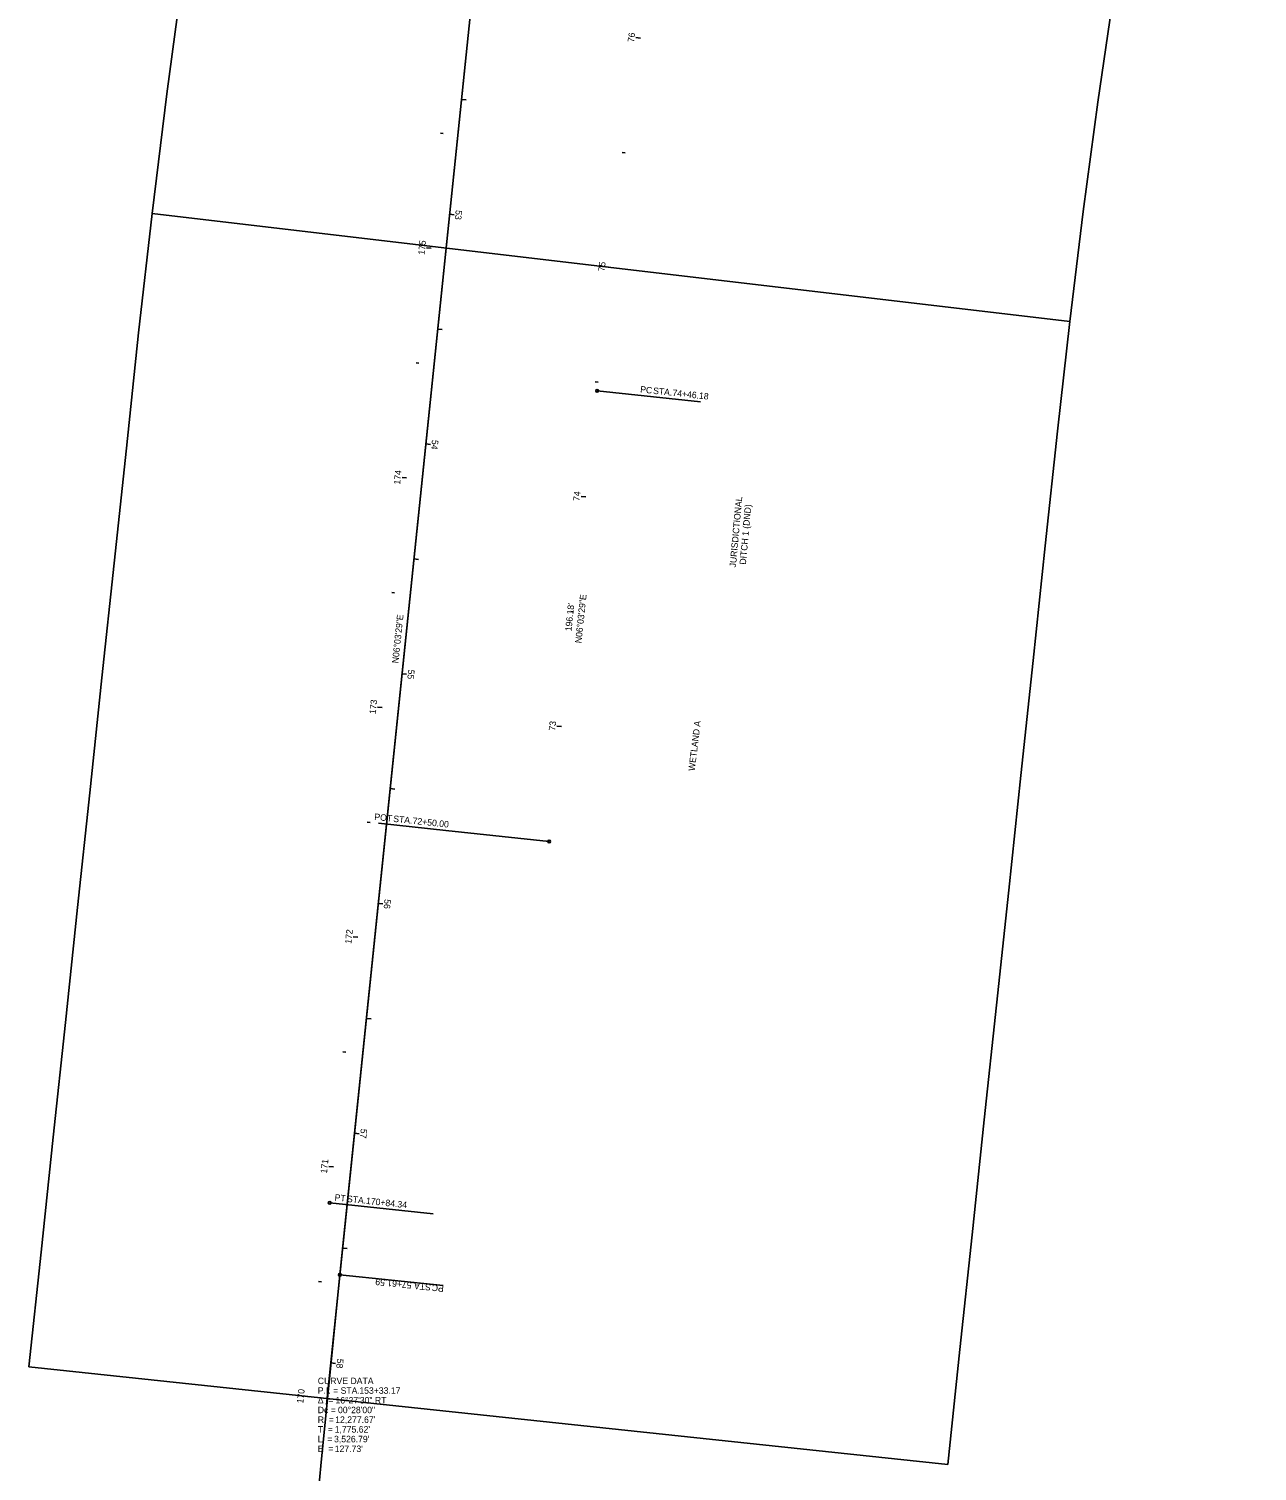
# Model space of a CAD drawing. Extents: x 172043 to 172958, y 249504 to 260295.
# Drawn here: x 172043 to 172574, y 253906 to 254530 of the extents above; entities that cross this region are included whole.
import ezdxf

# ---------------------------------------------------------------- set-up
doc = ezdxf.new("R2010")
doc.units = 0
for name, color, linetype in [('DR_X_Storm_Sewer', 7, 'Continuous'), ('LT_X_Poles', 7, 'Continuous'), ('PV_X_EOP', 7, 'Continuous'), ('RD_X_Fence', 7, 'Continuous'), ('RS_Raster1', 7, 'Continuous'), ('RW_X_CL_100_Bearings', 7, 'Continuous'), ('RW_X_CL_100_Curve_Data', 7, 'Continuous'), ('RW_X_CL_100_Distances', 7, 'Continuous'), ('RW_X_CL_100_Stations', 7, 'Continuous'), ('SC_Scratch1', 7, 'Continuous'), ('SV_X_Shot_Marker', 7, 'Continuous')]:
    doc.layers.add(name, color=color, linetype=linetype)

msp = doc.modelspace()

# ---------------------------------------------------------------- linework, layer by layer
at = {"layer": 'DR_X_Storm_Sewer'}
for points in [[(172095.96, 254450.44), (172493.22, 254403.68), (172499.07, 254451.2), (172505.42, 254498.65), (172512.28, 254546.03), (172519.63, 254593.34), (172527.5, 254640.57), (172535.86, 254687.71), (172544.72, 254734.76), (172554.08, 254781.71), (172563.94, 254828.56), (172574.32, 254875.56), (172184.15, 254963.66), (172172.96, 254913.01), (172162.22, 254862), (172152.03, 254810.88), (172142.38, 254759.66), (172133.28, 254708.34), (172124.72, 254656.92), (172116.71, 254605.42), (172109.24, 254553.83), (172102.33, 254502.17)], [(172042.63, 253950.99), (172440.4, 253908.78), (172445.67, 253958.5), (172450.95, 254008.22), (172456.23, 254057.94), (172461.5, 254107.66), (172466.78, 254157.38), (172472.06, 254207.1), (172477.34, 254256.82), (172482.61, 254306.54), (172487.87, 254356.1), (172493.22, 254403.68), (172095.96, 254450.44), (172090.14, 254398.64), (172084.85, 254348.76), (172079.57, 254299.04), (172074.29, 254249.32), (172069.02, 254199.6), (172063.74, 254149.88), (172058.46, 254100.16), (172053.18, 254050.44), (172047.91, 254000.71)]]:
    msp.add_lwpolyline(points, close=True, dxfattribs=at)
at = {"layer": 'PV_X_EOP'}
for p, q in [((172222, 254485.05), (172220.8, 254485.17)), ((172216.72, 254435.33), (172214.73, 254435.54)), ((172211.44, 254385.6), (172210.25, 254385.73)), ((172206.16, 254335.88), (172204.18, 254336.1)), ((172200.89, 254286.16), (172199.69, 254286.29)), ((172195.61, 254236.44), (172193.62, 254236.65)), ((172190.33, 254186.72), (172189.14, 254186.85)), ((172185.06, 254137), (172183.07, 254137.21)), ((172179.78, 254087.28), (172178.59, 254087.41)), ((172174.5, 254037.56), (172172.51, 254037.77)), ((172169.27, 253987.83), (172168.08, 253987.96)), ((172164.24, 253938.09), (172162.25, 253938.29))]:
    msp.add_line(p, q, dxfattribs=at)
at = {"layer": 'RW_X_CL_100_Bearings'}
for p, q in [((172288.6, 254373.57), (172333.35, 254368.82)), ((172193.92, 254186.34), (172223.15, 254183.24)), ((172267.9, 254178.49), (172223.15, 254183.24))]:
    msp.add_line(p, q, dxfattribs=at)
for centre in [(172288.6, 254373.57), (172267.9, 254178.49)]:
    msp.add_circle(centre, 0.6, dxfattribs=at)
at = {"layer": 'RW_X_CL_100_Stations'}
for p, q in [((172307.33, 254526.24), (172305.35, 254526.52)), ((172300.7, 254476.69), (172299.51, 254476.84)), ((172294.59, 254427.06), (172292.6, 254427.29)), ((172289.01, 254377.37), (172287.81, 254377.5)), ((172283.73, 254327.65), (172281.74, 254327.86)), ((172278.45, 254277.93), (172277.26, 254278.06)), ((172273.18, 254228.21), (172271.19, 254228.42)), ((172267.9, 254178.49), (172266.71, 254178.62))]:
    msp.add_line(p, q, dxfattribs=at)
at = {"layer": 'SC_Scratch1'}
for p, q in [((172428.67, 256423.35), (172177.28, 253990.91)), ((172409.1, 256234.03), (172171.47, 253934.66)), ((172229.87, 254499.79), (172231.86, 254499.58)), ((172224.73, 254450.05), (172226.72, 254449.84)), ((172219.59, 254400.31), (172221.58, 254400.11)), ((172214.45, 254350.58), (172216.44, 254350.37)), ((172209.31, 254300.84), (172211.3, 254300.64)), ((172204.17, 254251.11), (172206.16, 254250.9)), ((172199.03, 254201.37), (172201.02, 254201.17)), ((172193.89, 254151.64), (172195.88, 254151.43)), ((172188.75, 254101.9), (172190.74, 254101.7)), ((172183.61, 254052.17), (172185.6, 254051.96)), ((172178.47, 254002.43), (172180.46, 254002.23)), ((172177.28, 253990.91), (172222.04, 253986.28)), ((172173.39, 253952.69), (172175.38, 253952.49))]:
    msp.add_line(p, q, dxfattribs=at)
msp.add_circle((172177.28, 253990.91), 0.6, dxfattribs=at)
msp.add_arc((184611.06, 252705.91), 12500, 174.099581, 190.351353, dxfattribs=at)
msp.add_arc((184611.06, 252705.91), 12500, 174.099581, 190.351353, dxfattribs=at)
at = {"layer": 'SV_X_Shot_Marker'}
msp.add_line((172172.85, 254021.98), (172217.6, 254017.23), dxfattribs=at)
msp.add_circle((172172.85, 254021.98), 0.6, dxfattribs=at)

# ---------------------------------------------------------------- texts
at = {"layer": 'LT_X_Poles'}
for s, height, rotation, p in [('JURISDICTIONAL ', 2.8003, 84.8453, (172348.7, 254297.05)), ('DITCH 1 (DND)', 2.8003, 84.8453, (172353.03, 254298.25)), ('WETLAND A', 2.8, 83.01047, (172330.86, 254208.88))]:
    msp.add_text(s, height=height, rotation=rotation, dxfattribs=at).set_placement(p)
at = {"layer": 'PV_X_EOP'}
for s, rotation, p in [('175', 83.94188, (172213.89, 254432.4)), ('174', 83.94188, (172203.33, 254332.89)), ('173', 83.94188, (172192.79, 254233.53)), ('172', 83.94188, (172182.23, 254134.07)), ('171', 83.94188, (172171.68, 254034.62)), ('170', 84.33545, (172161.43, 253935.08))]:
    msp.add_text(s, height=2.8, rotation=rotation, dxfattribs=at).set_placement(p)
at = {"layer": 'RD_X_Fence'}
for s, p in [('CURVE DATA', (172167.7, 253943.55)), ('P.I. = STA. ', (172167.7, 253939.35)), ('153+33.17', (172185.69, 253939.35)), ('Δ  = ', (172167.7, 253935.15)), ('16°27\'30" RT', (172175.35, 253935.15)), ('Dc = ', (172167.7, 253930.95)), ('R  = ', (172167.7, 253926.75)), ("12,277.67'", (172175.24, 253926.75)), ('00°28\'00"', (172176.45, 253930.95)), ('T  = ', (172167.7, 253922.55)), ("1,775.62'", (172175.02, 253922.55)), ('L  = ', (172167.7, 253918.35)), ('E  = ', (172167.7, 253914.15)), ("3,526.79'", (172174.74, 253918.35)), ("127.73'", (172175.05, 253914.15))]:
    msp.add_text(s, height=2.8, dxfattribs=at).set_placement(p)
at = {"layer": 'RS_Raster1'}
msp.add_text('N06°03\'29"E', height=2.8, rotation=83.94188, dxfattribs=at).set_placement((172281.82, 254264.22))
at = {"layer": 'RW_X_CL_100_Bearings'}
for s, p in [('PC', (172307.16, 254372.92)), (' STA. ', (172311.72, 254372.43)), ('74+46.18', (172321.11, 254371.43)), ('POT', (172192.08, 254187.87)), (' STA. ', (172199.24, 254187.11)), ('72+50.00', (172208.64, 254186.12))]:
    msp.add_text(s, height=2.8, rotation=353.94188, dxfattribs=at).set_placement(p)
at = {"layer": 'RW_X_CL_100_Curve_Data'}
msp.add_text("196.18'", height=2.8, rotation=83.94188, dxfattribs=at).set_placement((172277.5, 254269.39))
at = {"layer": 'RW_X_CL_100_Distances'}
msp.add_text('N06°03\'29"E', height=2.8, rotation=83.94188, dxfattribs=at).set_placement((172202.58, 254255.52))
at = {"layer": 'RW_X_CL_100_Stations'}
for s, rotation, p in [('76', 82.07037, (172304.55, 254524.37)), ('75', 83.28703, (172291.85, 254425.18)), ('74', 83.94188, (172281.02, 254325.77)), ('73', 83.94188, (172270.46, 254226.33))]:
    msp.add_text(s, height=2.8, rotation=rotation, dxfattribs=at).set_placement(p)
at = {"layer": 'SC_Scratch1'}
for s, rotation, p in [('53', 264.09958, (172227.44, 254451.94)), ('54', 264.09958, (172217.16, 254352.47)), ('55', 264.09958, (172206.88, 254253.03)), ('56', 264.09958, (172196.61, 254153.61)), ('57', 264.09958, (172186.33, 254054.2)), ('57+61.59', 174.09958, (172208.42, 253987.65)), (' STA. ', 174.09958, (172217.82, 253986.68)), ('PC', 174.09958, (172222.38, 253986.2)), ('58', 264.27565, (172176.1, 253954.65))]:
    msp.add_text(s, height=2.8, rotation=rotation, dxfattribs=at).set_placement(p)
at = {"layer": 'SV_X_Shot_Marker'}
for s, p in [('PT', (172174.87, 254023.03)), (' STA. ', (172179.2, 254022.57)), ('170+84.34', (172188.47, 254021.58))]:
    msp.add_text(s, height=2.8, rotation=353.94188, dxfattribs=at).set_placement(p)

doc.saveas('drawing.dxf')
